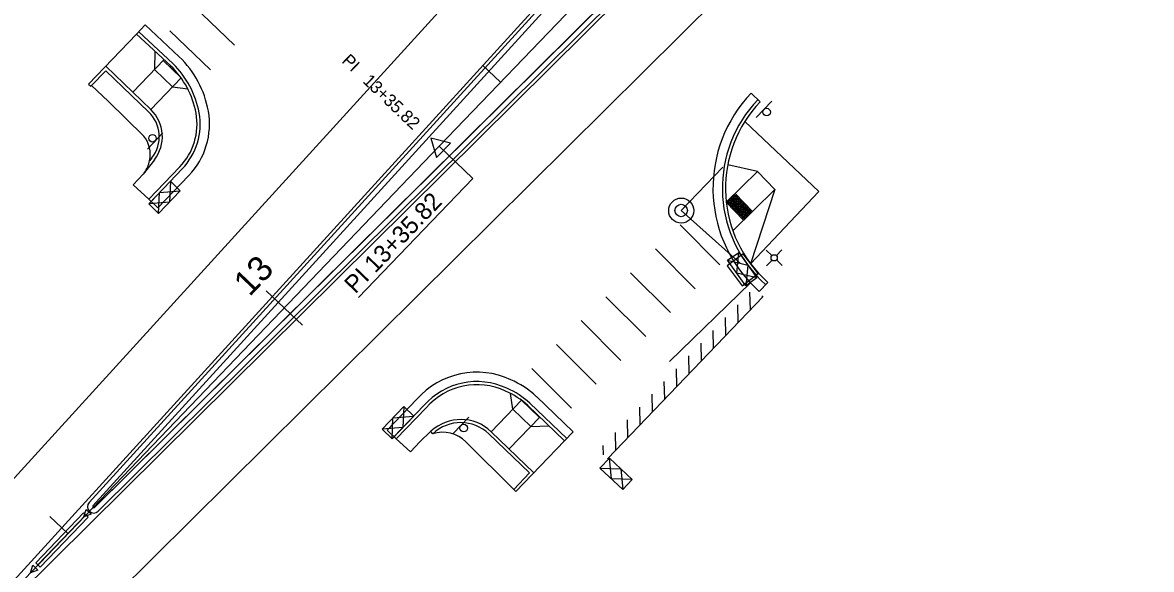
# Model space of a CAD drawing. Extents: x 2377903 to 2496516, y 664638 to 732785.
# Drawn here: x 2378076.4 to 2378256.9, y 730269.2 to 730356.6 of the extents above; entities that cross this region are included whole.
import ezdxf

# ---------------------------------------------------------------- set-up
doc = ezdxf.new("R2010")
doc.units = 0
for name, color, linetype in [('ALG_CL_BLUE_Horiz', 7, 'Continuous'), ('ALG_CL_BLUE_Horiz-PC-PT-PI', 7, 'Continuous'), ('ALG_CL_BLUE_Horiz-Stationing', 7, 'Continuous'), ('ALG_CL_BLUE_Horiz-Text', 7, 'Continuous'), ('Default', 7, 'Continuous'), ('DES_ROADWAY_Concrete-Pavement', 7, 'Continuous'), ('DES_ROADWAY_Curb-Back', 7, 'Continuous'), ('DES_ROADWAY_Curb-Face', 7, 'Continuous'), ('DES_ROADWAY_Curb-Face-LINE STYLE', 7, 'Continuous'), ('DES_ROADWAY_Edge-of-Pavement', 7, 'Continuous'), ('DES_ROADWAY_Misc-SAW CUT', 7, 'Continuous'), ('DES_ROADWAY_Sidewalk', 7, 'Continuous'), ('DES_ROADWAY_T-DOMES', 7, 'Continuous'), ('ENV_EROSN_Temp-Erosn-Ctrl-Details', 7, 'Continuous'), ('HYDR_Inlets', 7, 'Continuous'), ('TRAF_PAVEMARK_Stop-Bar', 7, 'Continuous'), ('TRAF_PAVEMARK_White_SKIP 12-38', 7, 'Continuous'), ('TRAF_PAVEMARK_Yellow', 7, 'Continuous'), ('TRAF_SIGN_Post', 7, 'Continuous'), ('TRAF_WORKZONE_Drum', 7, 'Continuous'), ('UTIL_STORM_Manhole', 7, 'Continuous'), ('UTIL_STORM_Pipe', 7, 'Continuous')]:
    doc.layers.add(name, color=color, linetype=linetype)

# ---------------------------------------------------------------- blocks, each defined once
blk = doc.blocks.new('MH_7')
at = {"layer": 'Default'}
for radius in [0.0254, 0.0127]:
    blk.add_circle((0, 0), radius, dxfattribs=at)
blk = doc.blocks.new('STSIGN_4')
at = {"layer": 'Default'}
for p, q in [((-0.0223, 0), (-0.0064, 0)), ((0, 0.0223), (0, 0.0064)), ((0.0064, 0), (0.0223, 0)), ((0, -0.0064), (0, -0.0223))]:
    blk.add_line(p, q, dxfattribs=at)
blk.add_circle((0, 0), 0.00635, dxfattribs=at)

msp = doc.modelspace()

# ---------------------------------------------------------------- linework, layer by layer
at = {"layer": 'ALG_CL_BLUE_Horiz'}
for p, q in [((2378143.04, 730336.85), (2378375.43, 730579.33)), ((2377910.62, 730094.46), (2378143.04, 730336.85))]:
    msp.add_line(p, q, dxfattribs=at)
at = {"layer": 'ALG_CL_BLUE_Horiz-PC-PT-PI'}
for p, q in [((2378143.04, 730336.85), (2378148.39, 730331.72)), ((2378148.39, 730331.72), (2378130.12, 730312.66))]:
    msp.add_line(p, q, dxfattribs=at)
at = {"layer": 'ALG_CL_BLUE_Horiz-Stationing'}
for p, q in [((2378149.96, 730349.85), (2378152.85, 730347.09)), ((2378115.36, 730313.76), (2378121.14, 730308.23)), ((2378080.76, 730277.67), (2378083.64, 730274.91))]:
    msp.add_line(p, q, dxfattribs=at)
msp.add_lwpolyline([(2378141.71, 730338.13), (2378142.6, 730335.06), (2378144.81, 730337.37)], close=True, dxfattribs=at)
at = {"layer": 'DES_ROADWAY_Concrete-Pavement'}
for p, q in [((2378087.64, 730279.33), (2378219.51, 730424.11)), ((2378226.97, 730416.96), (2378087.88, 730279.09)), ((2378097.09, 730335.01), (2378096.72, 730334.54))]:
    msp.add_line(p, q, dxfattribs=at)
for points in [[(2378095.81, 730338.49), (2378090.1, 730344.08), (2378087.42, 730346.56), (2378089.7, 730348.94), (2378096.56, 730342.37)], [(2378150.97, 730290.85), (2378157.47, 730284.62), (2378154.95, 730281.99), (2378147.29, 730289.6)]]:
    msp.add_lwpolyline(points, dxfattribs=at)
for centre, radius, start, end in [((2378092.75, 730338.4), 5.5, 321.9501, 46.2032), ((2378091.97, 730335.53), 4.85, 348.2632, 37.604), ((2378146.48, 730286.16), 6.5, 46.2032, 133.4205), ((2378143.6, 730285.9), 5.23, 45.1115, 107.6832), ((2378087.77, 730279.21), 0.167, 137.6727, 314.7476)]:
    msp.add_arc(centre, radius, start, end, dxfattribs=at)
at = {"layer": 'DES_ROADWAY_Curb-Back'}
for p, q in [((2378219.51, 730424.11), (2378087.64, 730279.33)), ((2378087.88, 730279.09), (2378226.97, 730416.96)), ((2378100.08, 730349.71), (2378094.64, 730354.81)), ((2378096.58, 730328.39), (2378101.55, 730333.57)), ((2378194.82, 730315.83), (2378195.59, 730315.08)), ((2378136.15, 730290.06), (2378140.92, 730295.05)), ((2378157.18, 730295.4), (2378163.06, 730289.74)), ((2378086.52, 730277.9), (2378078.85, 730269.91))]:
    msp.add_line(p, q, dxfattribs=at)
for centre, radius, start, end in [((2378090.46, 730339.69), 13.89, 10.1199, 46.181), ((2378208.8, 730330.13), 20, 136.1708, 225.6657), ((2378094.42, 730340.4), 9.87, 316.2239, 10.1199), ((2378149.04, 730287.96), 10.77, 64.7249, 138.9016), ((2378148.86, 730286.5), 12.18, 46.9182, 66.8976), ((2378087.77, 730279.21), 0.167, 137.6727, 314.7476)]:
    msp.add_arc(centre, radius, start, end, dxfattribs=at)
at = {"layer": 'DES_ROADWAY_Curb-Face'}
for p, q in [((2378086.16, 730278.25), (2378078.49, 730270.25)), ((2378086.88, 730277.56), (2378079.21, 730269.56)), ((2378086.16, 730278.25), (2378086.88, 730277.56)), ((2378078.49, 730270.25), (2378079.21, 730269.56))]:
    msp.add_line(p, q, dxfattribs=at)
at = {"layer": 'DES_ROADWAY_Curb-Face-LINE STYLE'}
for p, q in [((2378096.95, 730328.05), (2378101.91, 730333.23)), ((2378194.47, 730315.47), (2378195.24, 730314.72)), ((2378140.55, 730295.38), (2378135.79, 730290.41))]:
    msp.add_line(p, q, dxfattribs=at)
for points in [[(2378100.42, 730350.08), (2378100.42, 730350.08), (2378094.98, 730355.18)], [(2378163.41, 730290.1), (2378157.53, 730295.76), (2378157.52, 730295.76)]]:
    msp.add_lwpolyline(points, dxfattribs=at)
for centre, radius, start, end in [((2378090.46, 730339.69), 14.39, 10.1199, 46.181), ((2378208.8, 730330.13), 20.5, 136.1708, 225.6657), ((2378094.42, 730340.4), 10.37, 316.2239, 10.1199), ((2378149.04, 730287.96), 11.27, 64.7732, 138.8418), ((2378148.86, 730286.5), 12.68, 46.9182, 66.8548)]:
    msp.add_arc(centre, radius, start, end, dxfattribs=at)
at = {"layer": 'DES_ROADWAY_Edge-of-Pavement'}
for p, q in [((2378218.91, 730424.68), (2378087.03, 730279.89)), ((2378088.47, 730278.5), (2378227.57, 730416.38)), ((2378094.64, 730354.81), (2378096.01, 730356.27)), ((2378194.37, 730343.98), (2378192.92, 730345.37)), ((2378098.03, 730327.01), (2378102.99, 730332.19)), ((2378096.58, 730328.39), (2378098.03, 730327.01)), ((2378193.42, 730314.4), (2378194.19, 730313.65)), ((2378195.59, 730315.08), (2378194.19, 730313.65)), ((2378169.94, 730286.87), (2378194.85, 730312.86)), ((2378134.71, 730291.45), (2378139.45, 730296.4)), ((2378136.15, 730290.06), (2378134.71, 730291.45)), ((2378163.06, 730289.74), (2378164.45, 730291.18))]:
    msp.add_line(p, q, dxfattribs=at)
for points in [[(2378101.46, 730351.16), (2378101.45, 730351.17), (2378096.01, 730356.27)], [(2378158.55, 730296.86), (2378158.56, 730296.85), (2378164.45, 730291.18)]]:
    msp.add_lwpolyline(points, dxfattribs=at)
for centre, radius, start, end in [((2378090.46, 730339.69), 15.89, 10.1199, 46.181), ((2378208.8, 730330.13), 22, 136.1708, 225.6657), ((2378094.42, 730340.4), 11.87, 316.2239, 10.1199), ((2378149.04, 730287.96), 12.77, 64.8958, 138.6838), ((2378148.86, 730286.5), 14.18, 46.9182, 66.7451), ((2378087.77, 730279.21), 1, 137.6727, 314.7476)]:
    msp.add_arc(centre, radius, start, end, dxfattribs=at)
at = {"layer": 'DES_ROADWAY_Misc-SAW CUT'}
for p, q in [((2378192.78, 730310.71), (2378192.72, 730313.54)), ((2378194.74, 730312.75), (2378194.73, 730312.96)), ((2378194.74, 730312.75), (2378194.73, 730312.96)), ((2378190.82, 730308.67), (2378190.76, 730311.49)), ((2378188.87, 730306.62), (2378188.81, 730309.45)), ((2378186.91, 730304.58), (2378186.85, 730307.41)), ((2378184.95, 730302.54), (2378184.89, 730305.37)), ((2378182.99, 730300.5), (2378182.94, 730303.32)), ((2378181.04, 730298.45), (2378180.98, 730301.28)), ((2378179.08, 730296.41), (2378179.02, 730299.24)), ((2378177.12, 730294.37), (2378177.06, 730297.2)), ((2378175.16, 730292.33), (2378175.11, 730295.16)), ((2378173.21, 730290.28), (2378173.15, 730293.11)), ((2378171.25, 730288.24), (2378171.19, 730291.07)), ((2378169.27, 730287.51), (2378169.23, 730289.03))]:
    msp.add_line(p, q, dxfattribs=at)
at = {"layer": 'DES_ROADWAY_Sidewalk'}
for p, q in [((2378094.64, 730354.81), (2378086.95, 730346.79)), ((2378097.56, 730352.08), (2378097.48, 730349.11)), ((2378089.69, 730349.65), (2378096.91, 730342.73)), ((2378099.02, 730350.71), (2378094.02, 730345.5)), ((2378098.86, 730350.55), (2378101.75, 730347.78)), ((2378089.7, 730348.94), (2378087.31, 730346.45)), ((2378089.7, 730348.94), (2378096.56, 730342.37)), ((2378097.48, 730349.11), (2378100.37, 730346.34)), ((2378086.95, 730346.79), (2378087.31, 730346.45)), ((2378101.75, 730347.78), (2378096.91, 730342.73)), ((2378100.37, 730346.34), (2378102.83, 730346.02)), ((2378203.74, 730329.65), (2378191.89, 730340.82)), ((2378097.48, 730334.7), (2378095.68, 730332.41)), ((2378097.09, 730335.01), (2378096.72, 730334.54)), ((2378193.93, 730332.81), (2378189.16, 730333.91)), ((2378094.1, 730330.68), (2378095.68, 730332.41)), ((2378188.92, 730327.92), (2378193.93, 730332.81)), ((2378196.72, 730329.95), (2378193.93, 730332.81)), ((2378094.1, 730330.68), (2378096.58, 730328.39)), ((2378189.98, 730323.36), (2378196.72, 730329.95)), ((2378196.72, 730329.95), (2378192.83, 730318.08)), ((2378203.74, 730329.65), (2378192.83, 730318.08)), ((2378191.71, 730325.06), (2378188.92, 730327.92)), ((2378154.78, 730294.82), (2378154.42, 730297.34)), ((2378156.16, 730296.27), (2378151.32, 730291.21)), ((2378159.05, 730293.5), (2378156.16, 730296.27)), ((2378157.67, 730292.05), (2378154.78, 730294.82)), ((2378159.1, 730293.55), (2378154.21, 730288.45)), ((2378157.67, 730292.05), (2378160.54, 730292.16)), ((2378141.7, 730291.28), (2378139.91, 730289.61)), ((2378142.01, 730290.88), (2378141.67, 730291.25)), ((2378157.47, 730284.62), (2378150.97, 730290.85)), ((2378158.18, 730284.64), (2378151.32, 730291.21)), ((2378138.45, 730287.99), (2378136.15, 730290.06)), ((2378138.45, 730287.99), (2378139.91, 730289.61)), ((2378163.06, 730289.74), (2378155.3, 730281.64)), ((2378157.47, 730284.62), (2378154.94, 730281.99)), ((2378154.94, 730281.99), (2378155.3, 730281.64))]:
    msp.add_line(p, q, dxfattribs=at)
for centre, radius, start, end in [((2378092.75, 730338.4), 6, 321.9501, 46.2032), ((2378092.75, 730338.4), 5.5, 321.9501, 46.2032), ((2378091.97, 730335.53), 4.85, 323.9754, 348.2632), ((2378146.48, 730286.16), 7, 46.2032, 133.0057), ((2378146.48, 730286.16), 6.5, 46.2032, 133.4205)]:
    msp.add_arc(centre, radius, start, end, dxfattribs=at)
at = {"layer": 'DES_ROADWAY_T-DOMES'}
for p, q in [((2378193.14, 730326.45), (2378190.35, 730329.31)), ((2378191.71, 730325.06), (2378188.92, 730327.92))]:
    msp.add_line(p, q, dxfattribs=at)
msp.add_lwpolyline([(2378190.35, 730329.31), (2378193.14, 730326.45), (2378191.71, 730325.06), (2378188.92, 730327.92)], close=True, dxfattribs=at)
for centre in [(2378189.33, 730328.04), (2378189.48, 730328.18), (2378189.62, 730328.32), (2378189.62, 730328.04), (2378189.76, 730328.18), (2378189.76, 730328.46), (2378189.9, 730328.04), (2378189.91, 730328.6), (2378189.9, 730328.32), (2378190.05, 730328.74), (2378190.05, 730328.46), (2378190.04, 730328.18), (2378190.19, 730328.6), (2378190.19, 730328.32), (2378190.18, 730328.03), (2378190.19, 730328.88), (2378190.33, 730328.46), (2378190.33, 730328.17), (2378190.34, 730329.02), (2378190.33, 730328.74), (2378190.47, 730328.31), (2378190.47, 730328.03), (2378190.48, 730328.88), (2378190.47, 730328.6), (2378190.61, 730328.45), (2378190.61, 730328.17), (2378190.62, 730328.74), (2378190.75, 730328.31), (2378190.75, 730328.03), (2378190.76, 730328.59), (2378190.89, 730328.17), (2378190.9, 730328.45), (2378191.03, 730328.02), (2378191.03, 730328.31), (2378191.17, 730328.16), (2378191.31, 730328.02), (2378189.19, 730327.91), (2378189.33, 730327.76), (2378189.47, 730327.62), (2378189.47, 730327.9), (2378189.61, 730327.48), (2378189.61, 730327.76), (2378189.75, 730327.33), (2378189.76, 730327.9), (2378189.75, 730327.62), (2378189.89, 730327.19), (2378189.9, 730327.75), (2378189.89, 730327.47), (2378190.03, 730327.05), (2378190.04, 730327.89), (2378190.04, 730327.61), (2378190.03, 730327.33), (2378190.17, 730327.19), (2378190.17, 730326.9), (2378190.18, 730327.75), (2378190.18, 730327.47), (2378190.31, 730327.04), (2378190.31, 730326.76), (2378190.32, 730327.89), (2378190.32, 730327.61), (2378190.32, 730327.33), (2378190.45, 730326.9), (2378190.45, 730326.62), (2378190.46, 730327.75), (2378190.46, 730327.46), (2378190.45, 730327.18), (2378190.59, 730326.76), (2378190.59, 730326.47), (2378190.6, 730327.6), (2378190.6, 730327.32), (2378190.59, 730327.04), (2378190.61, 730327.89), (2378190.73, 730326.61), (2378190.73, 730326.33), (2378190.74, 730327.46), (2378190.74, 730327.18), (2378190.73, 730326.9), (2378190.74, 730327.74), (2378190.87, 730326.47), (2378190.87, 730326.19), (2378190.88, 730327.32), (2378190.88, 730327.04), (2378190.87, 730326.75), (2378190.89, 730327.88), (2378190.88, 730327.6), (2378191.01, 730326.33), (2378191.02, 730327.18), (2378191.02, 730326.89), (2378191.01, 730326.61), (2378191.03, 730327.74), (2378191.02, 730327.46), (2378191.15, 730326.18), (2378191.16, 730327.03), (2378191.16, 730326.75), (2378191.15, 730326.47), (2378191.17, 730327.88), (2378191.17, 730327.6), (2378191.16, 730327.31), (2378191.3, 730326.89), (2378191.3, 730326.61), (2378191.29, 730326.32), (2378191.31, 730327.74), (2378191.31, 730327.45), (2378191.3, 730327.17), (2378191.44, 730326.75), (2378191.44, 730326.46), (2378191.43, 730326.18), (2378191.45, 730327.59), (2378191.45, 730327.31), (2378191.44, 730327.03), (2378191.45, 730327.88), (2378191.58, 730326.6), (2378191.58, 730326.32), (2378191.59, 730327.45), (2378191.59, 730327.17), (2378191.58, 730326.89), (2378191.59, 730327.73), (2378191.72, 730326.74), (2378191.72, 730326.46), (2378191.72, 730326.18), (2378191.73, 730327.31), (2378191.73, 730327.02), (2378191.73, 730327.59), (2378191.86, 730326.6), (2378191.86, 730326.32), (2378191.87, 730327.16), (2378191.87, 730326.88), (2378191.87, 730327.45), (2378192, 730326.46), (2378192, 730326.17), (2378192.01, 730327.3), (2378192.01, 730327.02), (2378192.01, 730326.74), (2378192.14, 730326.31), (2378192.15, 730327.16), (2378192.15, 730326.88), (2378192.14, 730326.6), (2378192.28, 730326.17), (2378192.29, 730327.02), (2378192.29, 730326.74), (2378192.28, 730326.45), (2378192.43, 730326.87), (2378192.43, 730326.59), (2378192.42, 730326.31), (2378192.57, 730326.73), (2378192.57, 730326.45), (2378192.56, 730326.17), (2378192.71, 730326.59), (2378192.71, 730326.31), (2378192.85, 730326.45), (2378191.01, 730326.04), (2378191.15, 730325.9), (2378191.29, 730326.04), (2378191.29, 730325.76), (2378191.43, 730325.9), (2378191.43, 730325.61), (2378191.57, 730326.04), (2378191.57, 730325.75), (2378191.57, 730325.47), (2378191.71, 730325.89), (2378191.71, 730325.61), (2378191.7, 730325.33), (2378191.85, 730325.75), (2378191.85, 730325.47), (2378191.86, 730326.03), (2378191.99, 730325.61), (2378191.99, 730325.89), (2378192.14, 730326.03), (2378192.13, 730325.75), (2378192.28, 730325.89), (2378192.42, 730326.03)]:
    msp.add_circle(centre, 0.0375, dxfattribs=at)
at = {"layer": 'ENV_EROSN_Temp-Erosn-Ctrl-Details'}
for points in [[(2378096.57, 730327.65), (2378100.03, 730331.26), (2378101.61, 730329.74), (2378098.15, 730326.13)], [(2378192.05, 730314.54), (2378189.15, 730318.62), (2378190.95, 730319.89), (2378193.84, 730315.81)], [(2378138.94, 730293.7), (2378135.48, 730290.09), (2378133.89, 730291.61), (2378137.35, 730295.22)], [(2378172.37, 730281.98), (2378168.72, 730285.4), (2378170.23, 730287), (2378173.88, 730283.58)]]:
    msp.add_lwpolyline(points, close=True, dxfattribs=at)
for points in [[(2378100.03, 730331.26), (2378099.88, 730327.94), (2378096.57, 730327.65)], [(2378098.15, 730326.13), (2378098.3, 730329.46), (2378101.61, 730329.74)], [(2378193.84, 730315.81), (2378190.6, 730316.58), (2378190.95, 730319.89)], [(2378189.15, 730318.62), (2378192.39, 730317.85), (2378192.05, 730314.54)], [(2378137.35, 730295.22), (2378137.21, 730291.89), (2378133.89, 730291.61)], [(2378135.48, 730290.09), (2378135.62, 730293.41), (2378138.94, 730293.7)], [(2378173.88, 730283.58), (2378170.55, 730283.69), (2378170.23, 730287)], [(2378168.72, 730285.4), (2378172.05, 730285.29), (2378172.37, 730281.98)]]:
    msp.add_lwpolyline(points, dxfattribs=at)
at = {"layer": 'HYDR_Inlets'}
msp.add_lwpolyline([(2378194.04, 730316.49), (2378191.63, 730319.68), (2378189.08, 730317.74), (2378191.49, 730314.56)], close=True, dxfattribs=at)
at = {"layer": 'TRAF_PAVEMARK_Stop-Bar'}
for p, q in [((2378103.76, 730359.27), (2378110.26, 730353.04)), ((2378099.95, 730355.3), (2378106.45, 730349.07)), ((2378187.91, 730317.9), (2378181.55, 730324.27)), ((2378183.96, 730314.08), (2378177.59, 730320.44)), ((2378180, 730310.26), (2378173.64, 730316.62)), ((2378179.83, 730302.44), (2378192.83, 730315.01)), ((2378176.04, 730306.43), (2378169.68, 730312.8)), ((2378172.09, 730302.61), (2378165.72, 730308.98)), ((2378168.13, 730298.79), (2378161.77, 730305.16)), ((2378164.17, 730294.97), (2378157.81, 730301.34))]:
    msp.add_line(p, q, dxfattribs=at)
at = {"layer": 'TRAF_PAVEMARK_White_SKIP 12-38'}
for p, q in [((2378210.52, 730432.55), (2378065.28, 730273.09)), ((2378082.74, 730256.63), (2378235.84, 730408.38))]:
    msp.add_line(p, q, dxfattribs=at)
at = {"layer": 'TRAF_PAVEMARK_Yellow'}
for p, q in [((2378218.65, 730425.15), (2378073.42, 730265.68)), ((2378074.99, 730264.44), (2378227.99, 730416.1))]:
    msp.add_line(p, q, dxfattribs=at)
at = {"layer": 'TRAF_SIGN_Post'}
for p, q in [((2378193.71, 730341.45), (2378196.2, 730344.05)), ((2378098.85, 730339.02), (2378096.36, 730336.42)), ((2378145.26, 730290.91), (2378147.75, 730293.51))]:
    msp.add_line(p, q, dxfattribs=at)
for centre in [(2378195.39, 730342.33), (2378097.17, 730338.14), (2378146.94, 730291.79)]:
    msp.add_circle(centre, 0.6, dxfattribs=at)
at = {"layer": 'TRAF_WORKZONE_Drum'}
for points in [[(2378086.21, 730277.58), (2378086.58, 730278.78), (2378087.39, 730278)], [(2378077.64, 730268.65), (2378078.01, 730269.85), (2378078.83, 730269.07)]]:
    msp.add_lwpolyline(points, close=True, dxfattribs=at)
at = {"layer": 'UTIL_STORM_Pipe'}
for q in [(2378188.38, 730333.53), (2378191.23, 730318.12)]:
    msp.add_line((2378181.72, 730326.58), q, dxfattribs=at)

# ---------------------------------------------------------------- block references
at = {"layer": 'TRAF_SIGN_Post', "xscale": 78.74000000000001, "yscale": 78.74000000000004, "rotation": -43.30484086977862}
msp.add_blockref('STSIGN_4', (2378196.59, 730319.02), dxfattribs=at)
at = {"layer": 'UTIL_STORM_Manhole', "xscale": 78.74000000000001, "yscale": 78.74000000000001}
msp.add_blockref('MH_7', (2378181.72, 730326.58), dxfattribs=at)

# ---------------------------------------------------------------- texts
at = {"layer": 'ALG_CL_BLUE_Horiz-PC-PT-PI'}
msp.add_text('PI 13+35.82', height=2.8, rotation=46.1779, dxfattribs=at).set_placement((2378129.61, 730313.16))
at = {"layer": 'ALG_CL_BLUE_Horiz-Stationing'}
msp.add_text('13', height=4, rotation=46.2032, dxfattribs=at).set_placement((2378112.68, 730312.7))
at = {"layer": 'ALG_CL_BLUE_Horiz-Text'}
for s, p in [('PI', (2378127.32, 730350.37)), ('13+35.82', (2378130.68, 730347.15))]:
    msp.add_text(s, height=2, rotation=316.2068, dxfattribs=at).set_placement(p)

doc.saveas('drawing.dxf')
